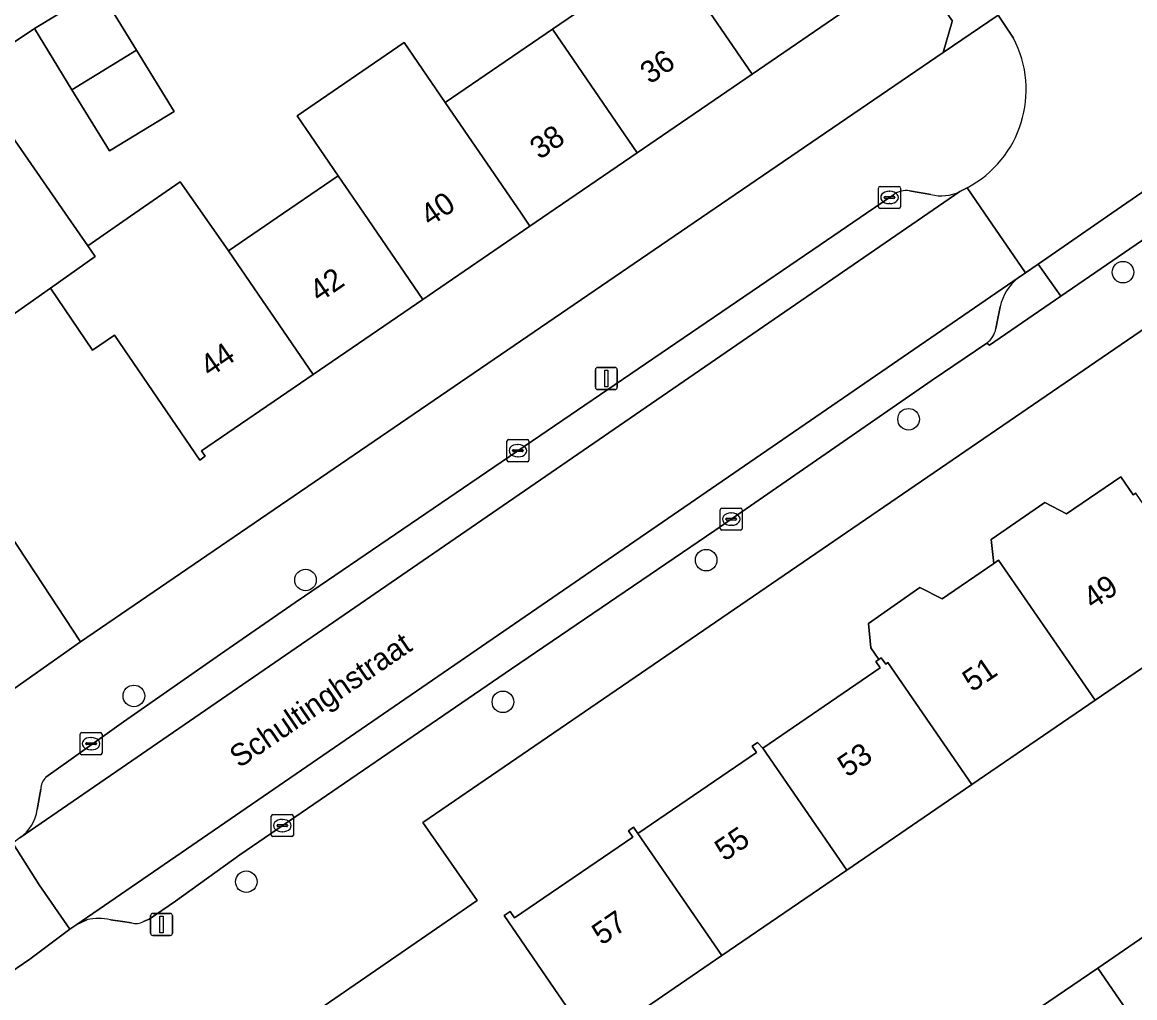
# Model space of a CAD drawing. Extents: x 157445 to 158888, y 383061 to 384688.
# Drawn here: x 158011.8 to 158062.3, y 383464.4 to 383508.7 of the extents above; entities that cross this region are included whole.
import ezdxf

# ---------------------------------------------------------------- set-up
doc = ezdxf.new("R2010")
doc.units = 0
for name, color, linetype in [('IMGEO_Boom', 7, 'Continuous'), ('IMGEO_Erf', 7, 'Continuous'), ('IMGEO_Kolk', 7, 'Continuous'), ('IMGEO_Lichtmast', 7, 'Continuous'), ('IMGEO_Muur', 7, 'Continuous'), ('IMGEO_Openbare_ruimte_label', 7, 'Continuous'), ('IMGEO_Pand', 7, 'Continuous'), ('IMGEO_Pand_nummerreeks', 7, 'Continuous'), ('IMGEO_Parkeervlak_open', 7, 'Continuous'), ('IMGEO_Rijbaan_lokaal_open', 7, 'Continuous'), ('IMGEO_Verkeerseiland_open', 7, 'Continuous'), ('IMGEO_Voetpad_open', 7, 'Continuous')]:
    doc.layers.add(name, color=color, linetype=linetype)

msp = doc.modelspace()

# ---------------------------------------------------------------- linework, layer by layer
at = {"layer": 'IMGEO_Boom'}
for centre in [(158061.721, 383497.327), (158051.991, 383490.656), (158042.807, 383484.266), (158024.628, 383483.364), (158016.839, 383478.107), (158033.584, 383477.838), (158021.939, 383469.679)]:
    msp.add_circle(centre, 0.489, dxfattribs=at)
at = {"layer": 'IMGEO_Erf'}
for points in [[(158001.189, 383500.638), (158012.356, 383483.697), (158014.419, 383480.567), (158042.879, 383500), (158053.556, 383507.29), (158053.975, 383508.693), (158053.979, 383508.706), (158043.18, 383524.51), (158040.79, 383522.974), (158042.19, 383520.871), (158034.565, 383515.761), (158032.809, 383518.397), (158031.211, 383520.798), (158030.279, 383520.173), (158029.39, 383521.428), (158029.144, 383521.255), (158025.602, 383526.256), (158028.696, 383528.448), (158025.217, 383533.359)], [(158015.265, 383510.171), (158016.964, 383507.396), (158018.664, 383504.622), (158015.729, 383502.824), (158014.029, 383505.598), (158012.33, 383508.373), (158009.303, 383506.368), (158013.717, 383500), (158014.744, 383498.519), (158016.88, 383500), (158018.944, 383501.431), (158019.936, 383500), (158021.131, 383498.293), (158023.628, 383500), (158026.114, 383501.699), (158024.249, 383504.421), (158029.104, 383507.739), (158030.969, 383505.017), (158035.836, 383508.343), (158041.058, 383511.911)], [(158049.449, 383509.426), (158044.895, 383506.312), (158039.674, 383502.742), (158035.665, 383500), (158034.808, 383499.414), (158029.954, 383496.094), (158024.972, 383492.687), (158019.906, 383489.223), (158020.076, 383488.976), (158019.829, 383488.807), (158015.958, 383494.471), (158014.968, 383493.794), (158013.051, 383496.601), (158010.946, 383495.114)], [(158067.298, 383497.916), (158029.951, 383472.367), (158032.414, 383468.826), (158013.037, 383455.497)], [(158036.471, 383464.018), (158033.646, 383468.143), (158033.912, 383468.326), (158034.11, 383468.038), (158039.476, 383471.705), (158039.278, 383471.993), (158039.51, 383472.151), (158039.708, 383471.863), (158045.09, 383475.542), (158044.892, 383475.83), (158045.14, 383475.999), (158045.382, 383475.741), (158050.704, 383479.379), (158050.506, 383479.667), (158050.638, 383479.757), (158050.277, 383480.285), (158050.175, 383481.391), (158052.499, 383483.023), (158053.518, 383482.508), (158055.863, 383484.11), (158055.731, 383485.207), (158058.173, 383486.882), (158059.164, 383486.372), (158061.616, 383488.048), (158062.18, 383487.222), (158062.297, 383487.302)], [(158057.226, 383463.47), (158060.574, 383465.765), (158063.434, 383467.726), (158064.902, 383465.584), (158067.594, 383467.412), (158065.285, 383470.782), (158066.628, 383471.63), (158068.465, 383471.158), (158071.813, 383473.453), (158074.673, 383475.414), (158076.141, 383473.272), (158081.707, 383477.087), (158076.382, 383484.808), (158073.284, 383482.661), (158068.001, 383479), (158067.92, 383479.118), (158065.612, 383477.539), (158063.794, 383480.197), (158060.453, 383477.912), (158054.857, 383474.084), (158049.186, 383470.205), (158043.514, 383466.325), (158037.89, 383462.478)]]:
    msp.add_lwpolyline(points, dxfattribs=at)
at = {"layer": 'IMGEO_Kolk'}
for p, q in [((158050.625, 383500.291), (158050.625, 383501.143)), ((158050.7, 383501.217), (158051.552, 383501.217)), ((158051.113, 383500.997), (158051.138, 383500.997)), ((158051.626, 383501.143), (158051.626, 383500.291)), ((158050.884, 383500.711), (158050.884, 383500.723)), ((158051.322, 383500.674), (158050.924, 383500.674)), ((158050.927, 383500.76), (158051.325, 383500.76)), ((158051.368, 383500.723), (158051.368, 383500.711)), ((158051.552, 383500.217), (158050.7, 383500.217)), ((158051.136, 383500.437), (158051.111, 383500.437)), ((158033.765, 383488.805), (158033.765, 383489.657)), ((158033.84, 383489.731), (158034.692, 383489.731)), ((158034.253, 383489.511), (158034.278, 383489.511)), ((158034.766, 383489.657), (158034.766, 383488.805)), ((158034.024, 383489.225), (158034.024, 383489.237)), ((158034.462, 383489.188), (158034.064, 383489.188)), ((158034.067, 383489.274), (158034.465, 383489.274)), ((158034.276, 383488.951), (158034.251, 383488.951)), ((158034.508, 383489.237), (158034.508, 383489.225)), ((158034.692, 383488.731), (158033.84, 383488.731)), ((158043.443, 383485.7), (158043.443, 383486.552)), ((158043.518, 383486.626), (158044.37, 383486.626)), ((158043.931, 383486.406), (158043.956, 383486.406)), ((158044.444, 383486.552), (158044.444, 383485.7)), ((158043.702, 383486.12), (158043.702, 383486.132)), ((158044.14, 383486.083), (158043.742, 383486.083)), ((158043.745, 383486.169), (158044.143, 383486.169)), ((158043.954, 383485.846), (158043.929, 383485.846)), ((158044.186, 383486.132), (158044.186, 383486.12)), ((158044.37, 383485.626), (158043.518, 383485.626)), ((158014.396, 383475.515), (158014.396, 383476.367)), ((158014.471, 383476.441), (158015.323, 383476.441)), ((158015.397, 383476.367), (158015.397, 383475.515)), ((158014.655, 383475.935), (158014.655, 383475.947)), ((158015.093, 383475.898), (158014.695, 383475.898)), ((158014.698, 383475.984), (158015.096, 383475.984)), ((158014.884, 383476.221), (158014.909, 383476.221)), ((158015.139, 383475.947), (158015.139, 383475.935)), ((158015.323, 383475.441), (158014.471, 383475.441)), ((158014.907, 383475.661), (158014.882, 383475.661)), ((158023.149, 383472.724), (158024.001, 383472.724)), ((158023.074, 383471.798), (158023.074, 383472.65)), ((158023.333, 383472.218), (158023.333, 383472.23)), ((158023.376, 383472.267), (158023.774, 383472.267)), ((158023.562, 383472.504), (158023.587, 383472.504)), ((158023.817, 383472.23), (158023.817, 383472.218)), ((158024.075, 383472.65), (158024.075, 383471.798)), ((158024.001, 383471.724), (158023.149, 383471.724)), ((158023.771, 383472.181), (158023.373, 383472.181)), ((158023.585, 383471.944), (158023.56, 383471.944))]:
    msp.add_line(p, q, dxfattribs=at)
for points in [[(158050.625, 383500.291), (158050.625, 383501.143)], [(158050.7, 383501.217), (158051.552, 383501.217)], [(158051.626, 383501.143), (158051.626, 383500.291)], [(158051.552, 383500.217), (158050.7, 383500.217)], [(158033.765, 383488.805), (158033.765, 383489.657)], [(158033.84, 383489.731), (158034.692, 383489.731)], [(158034.766, 383489.657), (158034.766, 383488.805)], [(158034.692, 383488.731), (158033.84, 383488.731)], [(158043.443, 383485.7), (158043.443, 383486.552)], [(158043.518, 383486.626), (158044.37, 383486.626)], [(158044.444, 383486.552), (158044.444, 383485.7)], [(158044.37, 383485.626), (158043.518, 383485.626)], [(158014.396, 383475.515), (158014.396, 383476.367)], [(158014.471, 383476.441), (158015.323, 383476.441)], [(158015.397, 383476.367), (158015.397, 383475.515)], [(158015.323, 383475.441), (158014.471, 383475.441)], [(158023.149, 383472.724), (158024.001, 383472.724)], [(158023.074, 383471.798), (158023.074, 383472.65)], [(158024.075, 383472.65), (158024.075, 383471.798)], [(158024.001, 383471.724), (158023.149, 383471.724)]]:
    msp.add_lwpolyline(points, dxfattribs=at)
for centre, radius, start, end in [((158050.702, 383501.141), 0.0765, 91.552, 178.448), ((158050.702, 383501.141), 0.0765, 91.552, 178.448), ((158051.55, 383501.141), 0.0765, 1.552, 88.448), ((158051.55, 383501.141), 0.0765, 1.552, 88.448), ((158050.924, 383500.72), 0.0403, 85.8775, 175.7526), ((158050.921, 383500.71), 0.0366, 178.938, 274.7102), ((158051.325, 383500.717), 0.043, 264.8664, 352.4533), ((158051.329, 383500.722), 0.0386, 1.7309, 96.639), ((158050.702, 383500.293), 0.0765, 181.552, 268.448), ((158050.702, 383500.293), 0.0765, 181.552, 268.448), ((158051.55, 383500.293), 0.0765, 271.552, 358.448), ((158051.55, 383500.293), 0.0765, 271.552, 358.448), ((158033.842, 383489.655), 0.0765, 91.552, 178.448), ((158033.842, 383489.655), 0.0765, 91.552, 178.448), ((158034.69, 383489.655), 0.0765, 1.552, 88.448), ((158034.69, 383489.655), 0.0765, 1.552, 88.448), ((158034.064, 383489.234), 0.0403, 85.8775, 175.7526), ((158034.061, 383489.224), 0.0366, 178.938, 274.7102), ((158034.465, 383489.231), 0.043, 264.8664, 352.4533), ((158034.469, 383489.236), 0.0386, 1.7309, 96.639), ((158033.842, 383488.807), 0.0765, 181.552, 268.448), ((158033.842, 383488.807), 0.0765, 181.552, 268.448), ((158034.69, 383488.807), 0.0765, 271.552, 358.448), ((158034.69, 383488.807), 0.0765, 271.552, 358.448), ((158043.52, 383486.55), 0.0765, 91.552, 178.448), ((158043.52, 383486.55), 0.0765, 91.552, 178.448), ((158044.368, 383486.55), 0.0765, 1.552, 88.448), ((158044.368, 383486.55), 0.0765, 1.552, 88.448), ((158043.742, 383486.129), 0.0403, 85.8775, 175.7526), ((158043.739, 383486.119), 0.0366, 178.938, 274.7102), ((158044.143, 383486.126), 0.043, 264.8664, 352.4533), ((158044.147, 383486.131), 0.0386, 1.7309, 96.639), ((158043.52, 383485.702), 0.0765, 181.552, 268.448), ((158043.52, 383485.702), 0.0765, 181.552, 268.448), ((158044.368, 383485.702), 0.0765, 271.552, 358.448), ((158044.368, 383485.702), 0.0765, 271.552, 358.448), ((158014.473, 383476.365), 0.0765, 91.552, 178.448), ((158014.473, 383476.365), 0.0765, 91.552, 178.448), ((158015.321, 383476.365), 0.0765, 1.552, 88.448), ((158015.321, 383476.365), 0.0765, 1.552, 88.448), ((158014.695, 383475.944), 0.0403, 85.8775, 175.7526), ((158014.692, 383475.934), 0.0366, 178.938, 274.7102), ((158015.096, 383475.941), 0.043, 264.8664, 352.4533), ((158015.1, 383475.946), 0.0386, 1.7309, 96.639), ((158014.473, 383475.517), 0.0765, 181.552, 268.448), ((158014.473, 383475.517), 0.0765, 181.552, 268.448), ((158015.321, 383475.517), 0.0765, 271.552, 358.448), ((158015.321, 383475.517), 0.0765, 271.552, 358.448), ((158023.151, 383472.648), 0.0765, 91.552, 178.448), ((158023.151, 383472.648), 0.0765, 91.552, 178.448), ((158023.999, 383472.648), 0.0765, 1.552, 88.448), ((158023.999, 383472.648), 0.0765, 1.552, 88.448), ((158023.373, 383472.227), 0.0403, 85.8775, 175.7526), ((158023.37, 383472.217), 0.0366, 178.938, 274.7102), ((158023.774, 383472.224), 0.043, 264.8664, 352.4533), ((158023.778, 383472.229), 0.0386, 1.7309, 96.639), ((158023.151, 383471.8), 0.0765, 181.552, 268.448), ((158023.151, 383471.8), 0.0765, 181.552, 268.448), ((158023.999, 383471.8), 0.0765, 271.552, 358.448), ((158023.999, 383471.8), 0.0765, 271.552, 358.448)]:
    msp.add_arc(centre, radius, start, end, dxfattribs=at)
for centre, major_axis, ratio, start_param, end_param in [((158051.112, 383500.717), (-0.387, 0.002), 0.722429, 4.712389, 7.853982), ((158051.137, 383500.717), (-0.39, 0.002), 0.717154, 1.570796, 4.712389), ((158034.252, 383489.231), (-0.387, 0.002), 0.722429, 4.712389, 7.853982), ((158034.277, 383489.231), (-0.39, 0.002), 0.717154, 1.570796, 4.712389), ((158043.93, 383486.126), (-0.387, 0.002), 0.722429, 4.712389, 7.853982), ((158043.955, 383486.126), (-0.39, 0.002), 0.717154, 1.570796, 4.712389), ((158014.883, 383475.941), (-0.387, 0.002), 0.722429, 4.712389, 7.853982), ((158014.908, 383475.941), (-0.39, 0.002), 0.717154, 1.570796, 4.712389), ((158023.561, 383472.224), (-0.387, 0.002), 0.722429, 4.712389, 7.853982), ((158023.586, 383472.224), (-0.39, 0.002), 0.717154, 1.570796, 4.712389)]:
    msp.add_ellipse(centre, major_axis=major_axis, ratio=ratio, start_param=start_param, end_param=end_param, dxfattribs=at)
at = {"layer": 'IMGEO_Lichtmast'}
for p, q in [((158037.781, 383492.104), (158037.781, 383492.904)), ((158037.781, 383492.904), (158037.781, 383492.104)), ((158037.881, 383493.004), (158038.671, 383493.004)), ((158038.671, 383493.004), (158037.881, 383493.004)), ((158038.771, 383492.904), (158038.771, 383492.104)), ((158038.771, 383492.104), (158038.771, 383492.904)), ((158038.671, 383492.004), (158037.881, 383492.004)), ((158037.881, 383492.004), (158038.671, 383492.004)), ((158017.699, 383468.242), (158018.489, 383468.242)), ((158018.489, 383468.242), (158017.699, 383468.242)), ((158017.599, 383467.342), (158017.599, 383468.142)), ((158017.599, 383468.142), (158017.599, 383467.342)), ((158018.589, 383468.142), (158018.589, 383467.342)), ((158018.589, 383467.342), (158018.589, 383468.142)), ((158018.489, 383467.242), (158017.699, 383467.242)), ((158017.699, 383467.242), (158018.489, 383467.242))]:
    msp.add_line(p, q, dxfattribs=at)
for points in [[(158038.201, 383492.879), (158038.351, 383492.879), (158038.351, 383492.129), (158038.201, 383492.129), (158038.201, 383492.879)], [(158018.019, 383468.117), (158018.169, 383468.117), (158018.169, 383467.367), (158018.019, 383467.367), (158018.019, 383468.117)]]:
    msp.add_lwpolyline(points, dxfattribs=at)
for centre, start, end in [((158037.881, 383492.904), 90, 180), ((158037.881, 383492.904), 90, 180), ((158038.671, 383492.904), 0, 90), ((158038.671, 383492.904), 360, 90), ((158037.881, 383492.104), 180, 270), ((158037.881, 383492.104), 180, 270), ((158038.671, 383492.104), 270, 0), ((158038.671, 383492.104), 270, 0), ((158017.699, 383468.142), 90, 180), ((158017.699, 383468.142), 90, 180), ((158018.489, 383468.142), 0, 90), ((158018.489, 383468.142), 360, 90), ((158017.699, 383467.342), 180, 270), ((158017.699, 383467.342), 180, 270), ((158018.489, 383467.342), 270, 0), ((158018.489, 383467.342), 270, 0)]:
    msp.add_arc(centre, 0.1, start, end, dxfattribs=at)
at = {"layer": 'IMGEO_Muur'}
msp.add_lwpolyline([(158012.356, 383483.697), (158001.189, 383500.638)], dxfattribs=at)
at = {"layer": 'IMGEO_Pand'}
for points in [[(158041.058, 383511.911), (158044.895, 383506.312), (158049.449, 383509.426), (158049.619, 383509.179), (158049.867, 383509.349), (158045.665, 383515.456), (158045.418, 383515.286), (158045.602, 383515.017)], [(158039.674, 383502.742), (158044.895, 383506.312), (158041.058, 383511.911), (158035.836, 383508.343)], [(158016.964, 383507.396), (158015.265, 383510.171), (158012.33, 383508.373), (158014.029, 383505.598)], [(158039.674, 383502.742), (158035.836, 383508.343), (158030.969, 383505.017), (158034.406, 383500), (158034.808, 383499.414), (158035.665, 383500)], [(158026.114, 383501.699), (158027.278, 383500), (158029.954, 383496.094), (158034.808, 383499.414), (158034.406, 383500), (158030.969, 383505.017), (158029.104, 383507.739), (158024.249, 383504.421)], [(158016.964, 383507.396), (158014.029, 383505.598), (158015.729, 383502.824), (158018.664, 383504.622)], [(158013.051, 383496.601), (158015.08, 383498.035), (158014.744, 383498.519), (158013.717, 383500), (158009.303, 383506.368), (158005.096, 383503.397), (158007.495, 383500), (158010.946, 383495.114)], [(158026.114, 383501.699), (158023.628, 383500), (158021.131, 383498.293), (158024.972, 383492.687), (158029.954, 383496.094), (158027.278, 383500)], [(158013.051, 383496.601), (158014.968, 383493.794), (158015.958, 383494.471), (158019.829, 383488.807), (158020.076, 383488.976), (158019.906, 383489.223), (158024.972, 383492.687), (158021.131, 383498.293), (158019.936, 383500), (158018.944, 383501.431), (158016.88, 383500), (158014.744, 383498.519), (158015.08, 383498.035)], [(158062.297, 383487.302), (158062.18, 383487.222), (158061.616, 383488.048), (158059.164, 383486.372), (158058.173, 383486.882), (158055.731, 383485.207), (158055.863, 383484.11), (158056.078, 383484.261), (158060.453, 383477.912), (158063.794, 383480.197), (158065.612, 383477.539), (158067.92, 383479.118)], [(158050.638, 383479.757), (158050.754, 383479.836), (158050.952, 383479.548), (158051.054, 383479.618), (158054.857, 383474.084), (158060.453, 383477.912), (158056.078, 383484.261), (158055.863, 383484.11), (158053.518, 383482.508), (158052.499, 383483.023), (158050.175, 383481.391), (158050.277, 383480.285)], [(158050.638, 383479.757), (158050.506, 383479.667), (158050.704, 383479.379), (158045.382, 383475.741), (158049.186, 383470.205), (158054.857, 383474.084), (158051.054, 383479.618), (158050.952, 383479.548), (158050.754, 383479.836)], [(158045.382, 383475.741), (158045.14, 383475.999), (158044.892, 383475.83), (158045.09, 383475.542), (158039.708, 383471.863), (158043.514, 383466.325), (158049.186, 383470.205)], [(158039.708, 383471.863), (158039.51, 383472.151), (158039.278, 383471.993), (158039.476, 383471.705), (158034.11, 383468.038), (158033.912, 383468.326), (158033.646, 383468.143), (158036.471, 383464.018), (158037.838, 383462.021), (158038.086, 383462.191), (158037.89, 383462.478), (158043.514, 383466.325)], [(158062.044, 383463.625), (158064.902, 383465.584), (158063.434, 383467.726), (158060.574, 383465.765)], [(158062.044, 383463.625), (158060.574, 383465.765), (158057.226, 383463.47), (158058.694, 383461.328)]]:
    msp.add_lwpolyline(points, close=True, dxfattribs=at)
at = {"layer": 'IMGEO_Parkeervlak_open'}
msp.add_lwpolyline([(158072.544, 383507.812), (158061.214, 383500), (158057.875, 383497.698), (158058.899, 383496.245), (158064.396, 383500), (158073.599, 383506.286)], close=True, dxfattribs=at)
for points in [[(158011.667, 383471.672), (158054.318, 383500.98)], [(158053.005, 383500.847), (158052.035, 383501.02)], [(158051.31, 383500.842), (158050.08, 383500), (158047.985, 383498.566), (158024.581, 383482.639), (158024.163, 383482.35), (158020.774, 383480.005), (158016.371, 383476.929), (158013.993, 383475.236), (158012.842, 383474.414)], [(158056.963, 383497.069), (158014.251, 383467.733), (158014.707, 383467.951)], [(158055.951, 383494.769), (158056.144, 383495.757)], [(158017.27, 383467.871), (158017.536, 383467.986), (158018.721, 383468.801), (158021.648, 383470.896), (158033.976, 383479.341), (158043.198, 383485.616), (158053.066, 383492.422), (158055.543, 383494.114)], [(158012.619, 383473.882), (158012.451, 383472.958)], [(158015.775, 383467.955), (158016.322, 383467.872), (158016.731, 383467.81)]]:
    msp.add_lwpolyline(points, dxfattribs=at)
for centre, radius, start, end in [((158051.898, 383500.012), 1.017, 82.2713, 125.3172), ((158053.47, 383502.808), 2.015, 256.6702, 294.8978), ((158058.391, 383495.266), 2.3, 128.3826, 167.6695), ((158054.902, 383494.968), 1.068, 306.9029, 349.2595), ((158013.367, 383473.881), 0.748, 134.5766, 179.9392), ((158010.594, 383473.208), 1.874, 304.9402, 352.3233), ((158015.249, 383465.792), 2.226, 76.3347, 104.0945), ((158016.924, 383468.52), 0.736, 254.8349, 298.0788)]:
    msp.add_arc(centre, radius, start, end, dxfattribs=at)
at = {"layer": 'IMGEO_Rijbaan_lokaal_open'}
for points in [[(158063.539, 383513.205), (158061.62, 383515.977), (158059.949, 383514.788), (158054.624, 383511.124), (158056.053, 383508.984), (158056.75, 383507.94)], [(158054.647, 383501.157), (158055.441, 383500), (158057.294, 383497.298), (158057.875, 383497.698), (158061.214, 383500), (158072.544, 383507.812), (158073.425, 383508.419), (158070.949, 383512.329)], [(158010.93, 383465.347), (158012.114, 383466.171), (158013.925, 383467.527), (158012.545, 383469.533), (158011.346, 383471.434), (158009.313, 383470.112)]]:
    msp.add_lwpolyline(points, dxfattribs=at)
msp.add_lwpolyline([(158056.963, 383497.069), (158057.294, 383497.298), (158055.441, 383500), (158054.647, 383501.157), (158054.318, 383500.98), (158011.667, 383471.672), (158011.346, 383471.434), (158012.545, 383469.533), (158013.925, 383467.527), (158014.251, 383467.733)], close=True, dxfattribs=at)
msp.add_arc((158052.299, 383505.603), 5.028, 297.8437, 27.7053, dxfattribs=at)
at = {"layer": 'IMGEO_Verkeerseiland_open'}
for points in [[(158055.543, 383494.114), (158055.666, 383494.018), (158058.899, 383496.245), (158057.875, 383497.698), (158057.294, 383497.298), (158056.963, 383497.069)], [(158056.144, 383495.757), (158055.951, 383494.769)]]:
    msp.add_lwpolyline(points, dxfattribs=at)
for centre, radius, start, end in [((158058.391, 383495.266), 2.3, 128.3826, 167.6695), ((158054.902, 383494.968), 1.068, 306.9029, 349.2595)]:
    msp.add_arc(centre, radius, start, end, dxfattribs=at)
at = {"layer": 'IMGEO_Voetpad_open'}
for points in [[(158005.973, 383578.779), (158040.104, 383528.972), (158041.185, 383527.394), (158038.836, 383525.909), (158040.79, 383522.974), (158043.18, 383524.51), (158053.979, 383508.706), (158053.975, 383508.693), (158053.556, 383507.29), (158056.053, 383508.984), (158054.624, 383511.124), (158045.102, 383525.057), (158044.749, 383524.82), (158041.384, 383529.778), (158041.721, 383530.034), (158008.336, 383578.833)], [(158056.75, 383507.94), (158056.053, 383508.984), (158053.556, 383507.29), (158042.879, 383500), (158014.419, 383480.567), (158008.693, 383476.539), (158006.601, 383475.068)], [(158032.414, 383468.826), (158029.951, 383472.367), (158067.298, 383497.916), (158069.597, 383499.52), (158073.599, 383506.286), (158064.396, 383500), (158058.899, 383496.245), (158055.666, 383494.018), (158055.543, 383494.114), (158053.066, 383492.422), (158043.198, 383485.616), (158033.976, 383479.341), (158021.648, 383470.896), (158018.721, 383468.801), (158017.536, 383467.986), (158017.27, 383467.871)], [(158052.035, 383501.02), (158053.005, 383500.847)], [(158054.318, 383500.98), (158054.647, 383501.157)], [(158008.693, 383476.539), (158014.419, 383480.567), (158012.356, 383483.697), (158001.189, 383500.638)], [(158047.985, 383498.566), (158050.08, 383500), (158051.31, 383500.842)], [(158012.842, 383474.414), (158013.993, 383475.236), (158016.371, 383476.929), (158020.774, 383480.005), (158024.163, 383482.35), (158024.581, 383482.639), (158047.985, 383498.566)], [(158012.451, 383472.958), (158012.619, 383473.882)], [(158014.707, 383467.951), (158014.251, 383467.733), (158013.925, 383467.527), (158012.114, 383466.171), (158010.93, 383465.347), (158008.072, 383463.356), (158013.037, 383455.497), (158032.414, 383468.826)], [(158016.731, 383467.81), (158016.322, 383467.872), (158015.775, 383467.955)]]:
    msp.add_lwpolyline(points, dxfattribs=at)
msp.add_lwpolyline([(158022.011, 383514.66), (158021.699, 383515.093), (158022.224, 383515.472), (158020.039, 383518.82), (158018.49, 383521.194), (158016.469, 383524.288), (158013.542, 383528.823), (158011.787, 383527.601), (158014.242, 383524.015), (158016.039, 383521.39), (158017.816, 383518.792), (158019.772, 383515.834), (158010.049, 383508.984), (158008.072, 383507.536), (158004.038, 383504.58), (158000.328, 383501.854), (158001.189, 383500.638), (158005.096, 383503.397), (158009.303, 383506.368), (158012.33, 383508.373), (158015.265, 383510.171)], close=True, dxfattribs=at)
for centre, radius, start, end in [((158052.299, 383505.603), 5.028, 297.8437, 27.7053), ((158051.898, 383500.012), 1.017, 82.2713, 125.3172), ((158053.47, 383502.808), 2.015, 256.6702, 294.8978), ((158013.367, 383473.881), 0.748, 134.5766, 179.9392), ((158010.594, 383473.208), 1.874, 304.9402, 352.3233), ((158015.249, 383465.792), 2.226, 76.3347, 104.0945), ((158016.924, 383468.52), 0.736, 254.8349, 298.0788)]:
    msp.add_arc(centre, radius, start, end, dxfattribs=at)

# ---------------------------------------------------------------- texts
at = {"layer": 'IMGEO_Openbare_ruimte_label'}
msp.add_text('Schultinghstraat', height=1, rotation=34.3256, dxfattribs=at).set_placement((158021.622, 383474.81))
at = {"layer": 'IMGEO_Pand_nummerreeks'}
for s, rotation, p in [('36', 34.3669, (158040.252, 383505.827)), ('38', 34.3669, (158035.249, 383502.406)), ('40', 34.371, (158030.28, 383499.371)), ('42', 34.367, (158025.25, 383495.931)), ('44', 34.367, (158020.285, 383492.535)), ('49', 34.3489, (158060.356, 383482.002)), ('51', 34.3489, (158054.876, 383478.257)), ('53', 34.3489, (158049.21, 383474.385)), ('55', 34.3488, (158043.638, 383470.576)), ('57', 34.3488, (158038.065, 383466.768))]:
    msp.add_text(s, height=1, rotation=rotation, dxfattribs=at).set_placement(p)

doc.saveas('drawing.dxf')
